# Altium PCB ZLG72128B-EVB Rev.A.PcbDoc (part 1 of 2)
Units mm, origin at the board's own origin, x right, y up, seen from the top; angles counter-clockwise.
Board outline 130 x 80 mm, 2 copper layers (Top Layer, Bottom Layer); 109 components, 70 nets, 433 pads, 399 vias.
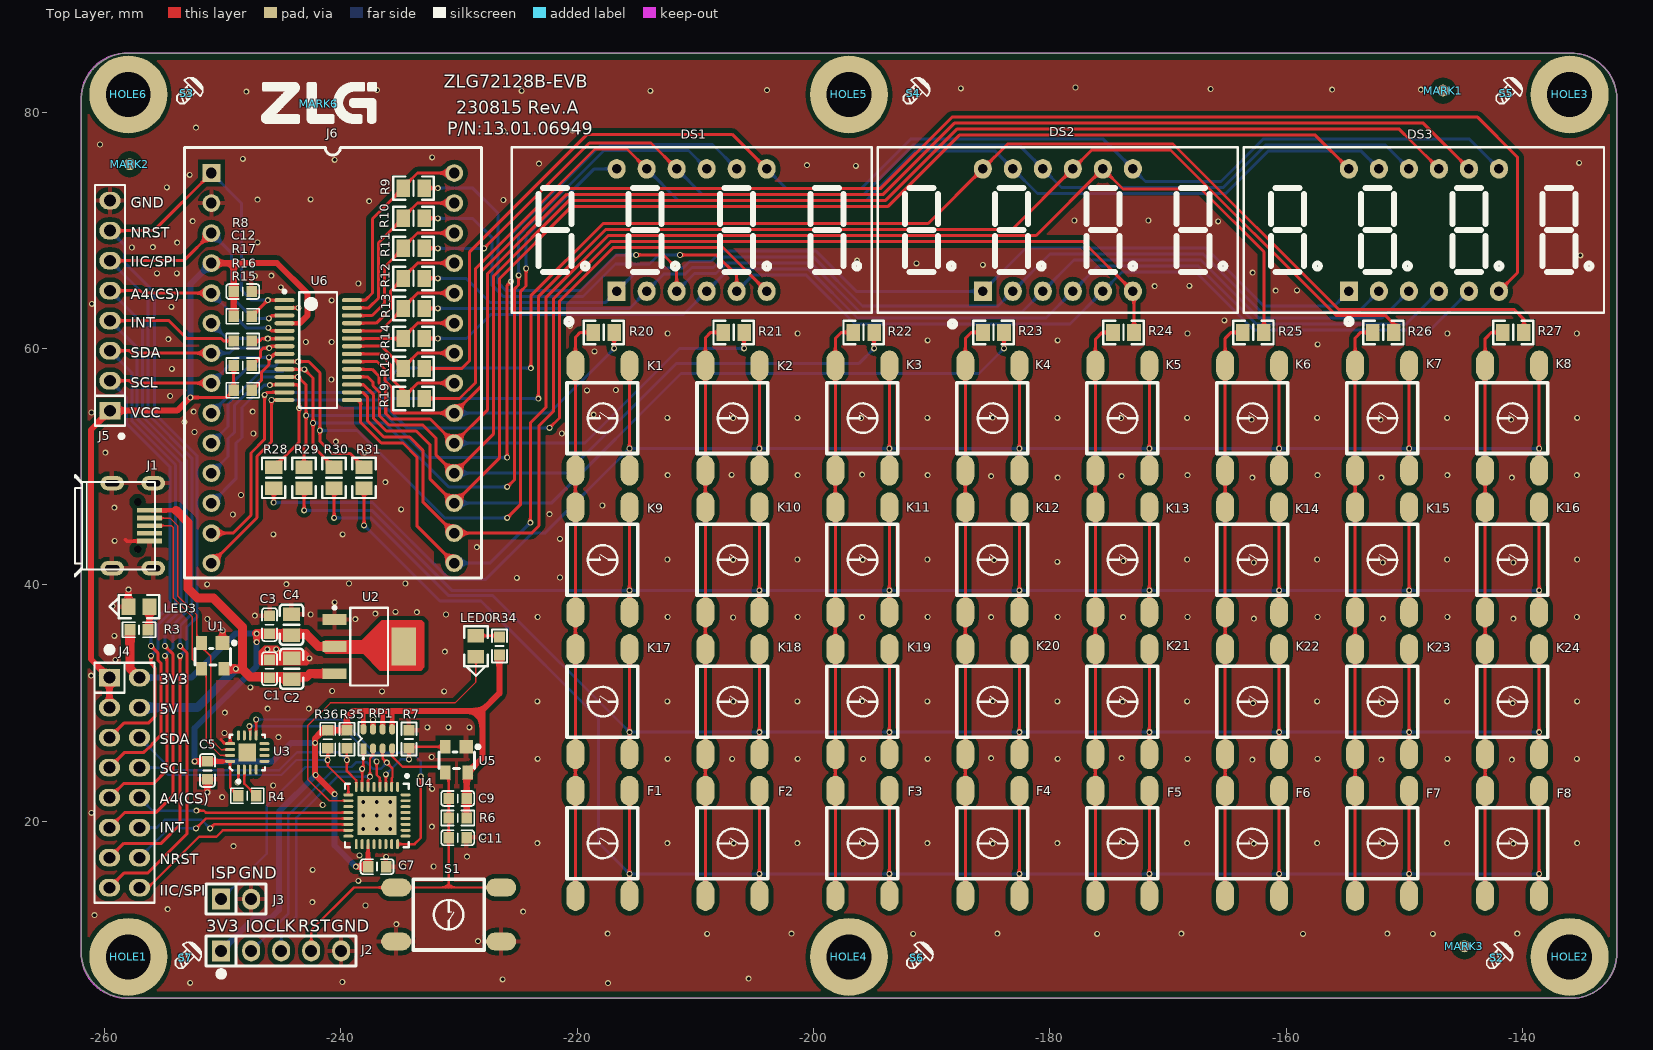
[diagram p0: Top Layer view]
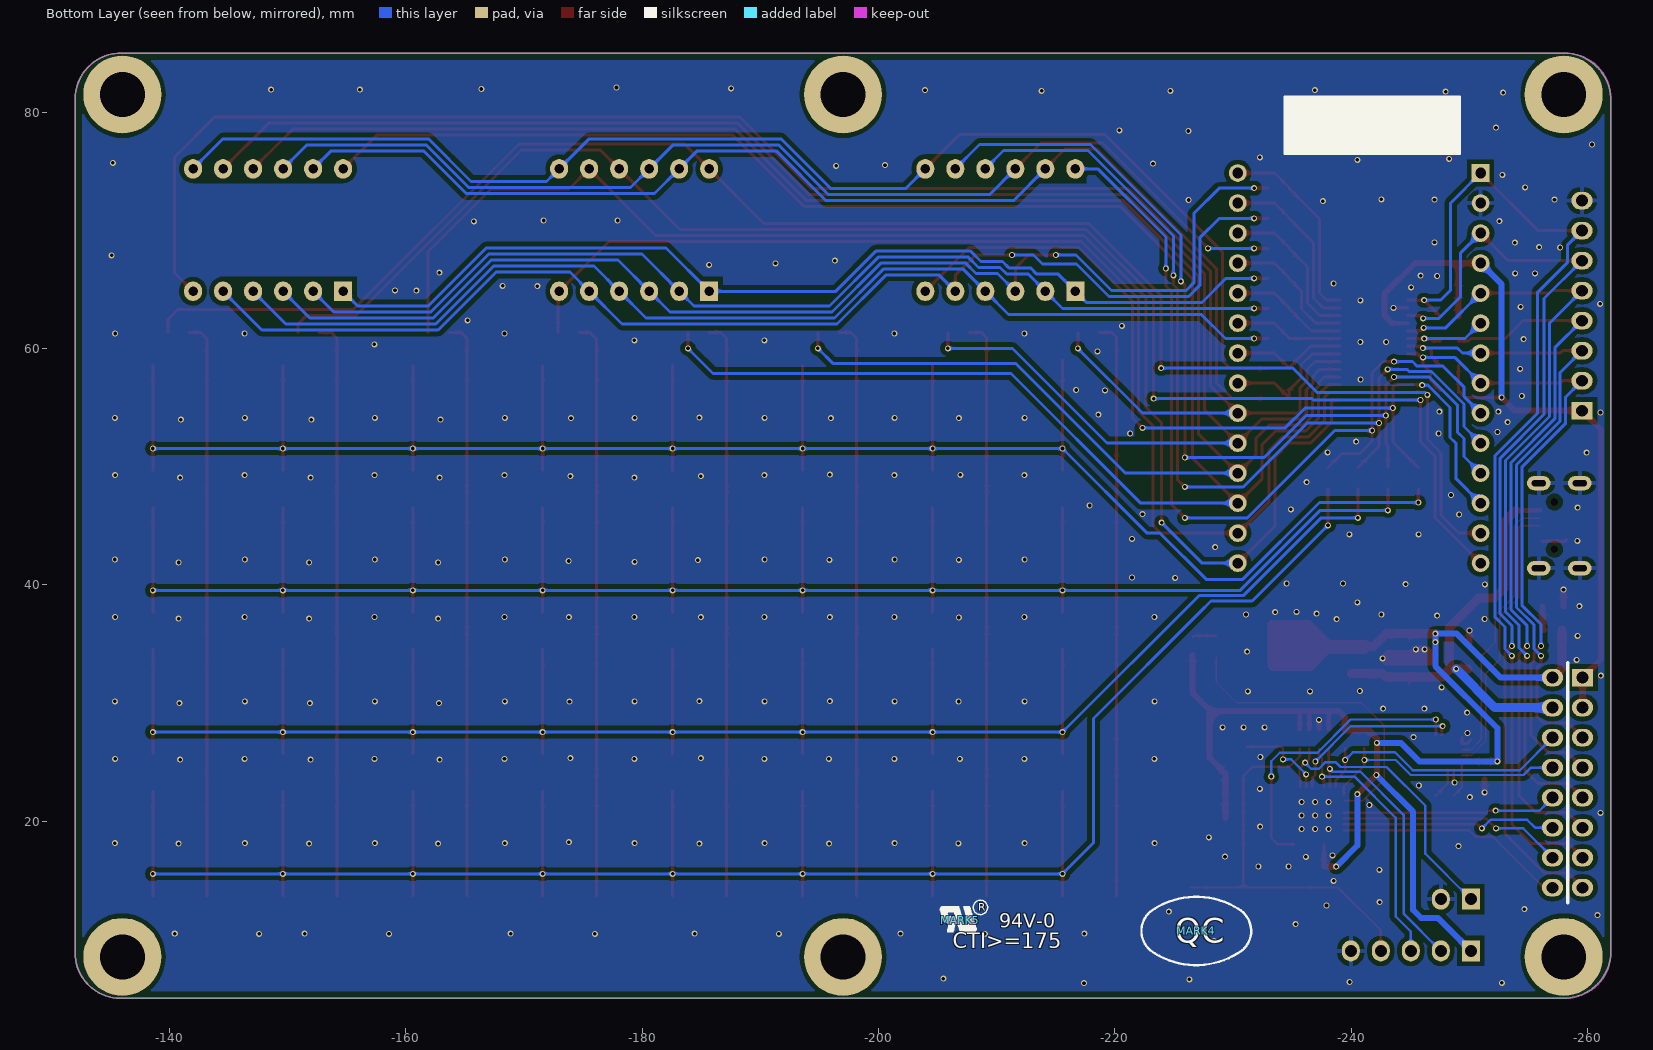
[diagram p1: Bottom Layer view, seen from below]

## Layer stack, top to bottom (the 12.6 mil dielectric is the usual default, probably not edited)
Top Solder: solder mask 0.0102, Solder Resist, Dk 3.5
Top Layer: signal copper 0.0356
Dielectric1: dielectric 0.32, FR-4, Dk 4.8
Bottom Layer: signal copper 0.0356
Bottom Solder: solder mask 0.0102, Solder Resist, Dk 3.5

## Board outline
-262,8.962 -262,80.911 cw(c-257.974,80.974) -258.038,85 -135.988,85 cw(c-135.912,81.088) -131.999,81.119 -132,81.119 -132,8.886 cw(c-135.848,8.848) -135.81,5 -257.911,5 cw(c-257.974,9.026)

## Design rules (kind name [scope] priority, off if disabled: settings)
Clearance Clearance_Keepout [OnLayer('Keep-Out Layer')] p1: gap=0.508 ignorepadtopadclearanceinfootprint=FALSE except(0: Arc-Hole Track-Hole SMDPad-Hole THPad-Hole Via-Hole Fill-Hole Poly-Hole Region-Hole Text-Hole)
Clearance Clearance_Wave [OnLayer('Bottom Layer') and IsSMTPin vs IsPadHoleValid>(HasFootprint('PAD-35/50') or HasFootprint('HOLE-3.2*') or HasFootprint('SMDSTUD-409D556W*') or    HasFootprint('SMT50L*FEMALE') or HasFootprint('IDCS*'))] p2: gap=4 ignorepadtopadclearanceinfootprint=FALSE except(0: Arc-Hole Track-Hole SMDPad-Hole THPad-Hole Via-Hole Fill-Hole Poly-Hole Region-Hole Text-Hole)
Clearance Clearance_Via2Via [IsVia vs IsVia] p3: gap=0.152 ignorepadtopadclearanceinfootprint=FALSE except(0: Arc-Hole Track-Hole SMDPad-Hole THPad-Hole Via-Hole Fill-Hole Poly-Hole Region-Hole Text-Hole)
Clearance Clearance_Poly2All [InPoly] p4: gap=0.381 ignorepadtopadclearanceinfootprint=FALSE except(0: Arc-Hole Track-Hole SMDPad-Hole THPad-Hole Via-Hole Fill-Hole Poly-Hole Region-Hole Text-Hole)
Clearance Clearance_TP [HasFootprint('PAD-40') vs HasFootprint('PAD-40')] p5: gap=1.27 ignorepadtopadclearanceinfootprint=FALSE except(0: Arc-Hole Track-Hole SMDPad-Hole THPad-Hole Via-Hole Fill-Hole Poly-Hole Region-Hole Text-Hole)
Clearance [All] p6: gap=0.127 ignorepadtopadclearanceinfootprint=FALSE except(0: Arc-Hole Track-Hole SMDPad-Hole THPad-Hole Via-Hole Fill-Hole Poly-Hole Region-Hole Text-Hole)
DiffPairsRouting [All] p1: maxlimit=0.203 minlimit=0.203 mostfreqgap=0.203 toplayer_minwidth=0.13 toplayer_maxwidth=0.13 toplayer_prefwidth=0.13 bottomlayer_minwidth=0.13 bottomlayer_maxwidth=0.13 bottomlayer_prefwidth=0.13 maxuncoupledlength=12.7
HoleSize [All] p1: absolutevalues=TRUE maxlimit=25.4 minlimit=0.025 maxpercent=80.000 minpercent=20.000
MinimumSolderMaskSliver [All] p1: minsoldermaskwidth=0.102
PlaneClearance PlaneClearance_Full [IsVia] p1: clearance=0.229
PlaneClearance [All] p2: clearance=0.508
PlaneConnect PlaneConnect_Full [IsVia] p1: planeconnectstyle=Direct reliefexpansion=0.508 reliefentries=4 reliefconductorwidth=0.254 reliefairgap=0.254
PlaneConnect [All] p2: planeconnectstyle=Relief reliefexpansion=0.254 reliefentries=4 reliefconductorwidth=0.381 reliefairgap=0.254
PolygonConnect PolygonConnect_SMDHole [HasFootprint('Mou Hole-300D450W310H-SMD') or HasFootprint('Mou Hole-373D600H-SMD')] p1: connectstyle=Relief reliefconductorwidth=2.032 reliefentries=4 polygonreliefangle="45 Angle" airgapwidth=0.508
PolygonConnect PolygonConnect_Full [IsVia or   HasFootprint('PAD-40') or  HasFootprint('PAD-35/50') or  HasFootprint('HOLE-3.2') or   HasFootprint('HOLE-3.2 - Screw')] p2: connectstyle=Direct reliefconductorwidth=0.254 reliefentries=4 polygonreliefangle="90 Angle" airgapwidth=0.254
PolygonConnect [All] p3: connectstyle=Relief reliefconductorwidth=0.381 reliefentries=4 polygonreliefangle="90 Angle" airgapwidth=0.381
RoutingVias [All] p1: holewidth=0.305 width=0.508 viastyle="Through Hole" minholewidth=0.305 minwidth=0.508 maxholewidth=0.305 maxwidth=0.508
SilkToSilkClearance [All  > IsTextInverted] p1: silktosilkclearance=0.051
SilkToSolderMaskClearance SilkToSolderMaskClearance_1 [IsComponentPad vs IsComponentArc or IsComponentTrack] p1: minsilkscreentomaskgap=0 clearancetoexposedcopper=TRUE
SilkToSolderMaskClearance [IsPad] p2: minsilkscreentomaskgap=0.051 clearancetoexposedcopper=TRUE
SolderMaskExpansion [All] p1: expansion=0.102 istentingtop=FALSE
Width [All] p1: maxlimit=2.54 minlimit=0.127 preferedwidth=0.127
23 further rules are at their usual default settings.

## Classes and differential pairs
component class "01.LPC824 最小系统": C7 C9 C11 HOLE1 HOLE2 HOLE3 HOLE4 HOLE5 HOLE6 HOLE? J2 J3 J4 MARK1 MARK2 MARK3 MARK4 MARK5 MARK6 MARK? R6 R7 R35 R36 RP1 S1 S2 S3 S4 S5 S6 S7 S? U4 U5
component class 02.ZLG72128B-key-digital: C12 DS1 DS2 DS3 F1 F2 F3 F4 F5 F6 F7 F8 J5 J6 K1 K2 K3 K4 K5 K6 K7 K8 K9 K10 K11 K12 K13 K14 K15 K16 K17 K18 K19 K20 K21 K22 K23 K24 R8 R9 R10 R11 R12 R13 R14 R15 R16 R17 R18 R19 R20 R21 R22 R23 R24 R25 R26 R27 R28 R29 R30 R31 U6
component class 03.USB和电源: C1 C2 C3 C4 C5 J1 LED0 LED3 R3 R4 R34 U1 U2 U3
differential pair USB: +USB_P -USB_N

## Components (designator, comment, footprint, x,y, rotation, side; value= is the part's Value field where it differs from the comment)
C1 "10μF,6.3V" 0603C -246.046,32.889 r90 top
C2 "105" 0805C -244.166,32.889 r270 top value=C2012X7R1E105KT000N,105
C3 "104,±10%" 0603C -246.046,36.623 r270 top
C4 "475,±10%" 0805C -244.192,36.623 r90 top
C5 "104,±10%" 0603C -251.306,24.291 r270 top
C7 "104,±10%" 0603C -236.941,16.139 r180 top
C9 "104,±10%" 0603C -230.12,21.916 r0 top
C11 "104,±10%" 0603C -230.12,18.589 r180 top
C12 "104" 0603C -248.313,64.817 r180 top value=104,±10%
DS1 "LN3461" LN3461-3000X1400X720 -210.308,70.024 r0 top locked value=LN3461AS,30×14×7.3mm
DS2 "LN3461" LN3461-3000X1400X720 -179.32,70.024 r0 top locked value=LN3461AS,30×14×7.3mm
DS3 "LN3461" LN3461-3000X1400X720 -148.332,70.024 r0 top locked value=LN3461AS,30×14×7.3mm
F1 "6×6×5.0mm,红色" KEY-6S -217.864,18.109 r270 top
F2 "6×6×5.0mm,红色" KEY-6S -206.864,18.109 r270 top
F3 "6×6×5.0mm,红色" KEY-6S -195.864,18.109 r270 top
F4 "6×6×5.0mm,红色" KEY-6S -184.864,18.109 r270 top
F5 "6×6×5.0mm,红色" KEY-6S -173.864,18.109 r270 top
F6 "6×6×5.0mm,红色" KEY-6S -162.864,18.109 r270 top
F7 "6×6×5.0mm,红色" KEY-6S -151.864,18.109 r270 top
F8 "6×6×5.0mm,红色" KEY-6S -140.864,18.109 r270 top
HOLE1 "HOLE" HOLE-3.8 -258,8.5 r0 top locked
HOLE2 "HOLE" HOLE-3.8 -136,8.5 r0 top locked
HOLE3 "HOLE" HOLE-3.8 -136,81.5 r0 top locked
HOLE4 "HOLE" HOLE-3.8 -197,8.5 r0 top locked
HOLE5 "HOLE" HOLE-3.8 -197,81.5 r0 top locked
HOLE6 "HOLE" HOLE-3.8 -258,81.5 r0 top locked
J1 "USB_MINIB_SMT" MICROUSB-5S -261.511,45 r270 top value=MicroUSB插座
J2 "SWD" SIP2.54-1X5 -245.055,9.013 r0 top
J3 "ISP" SIP2.54-1X2 -248.865,13.382 r0 top
J4 "HEADER 8X2" IDC-16-2.54 -259.595,32.14 r270 top locked
J5 "CON8" SIP-8-2.54 -259.543,54.733 r90 top locked
J6 "HEADER 14X2" zlg72128 -240.687,58.34 r0 top locked
K1 "6×6×5.0mm,黑色" KEY-6S -217.864,54.109 r270 top
K2 "6×6×5.0mm,黑色" KEY-6S -206.864,54.109 r270 top
K3 "6×6×5.0mm,黑色" KEY-6S -195.864,54.109 r270 top
K4 "6×6×5.0mm,黑色" KEY-6S -184.864,54.109 r270 top
K5 "6×6×5.0mm,黑色" KEY-6S -173.864,54.109 r270 top
K6 "6×6×5.0mm,黑色" KEY-6S -162.864,54.109 r270 top
K7 "6×6×5.0mm,黑色" KEY-6S -151.864,54.109 r270 top
K8 "6×6×5.0mm,黑色" KEY-6S -140.864,54.109 r270 top
K9 "6×6×5.0mm,黑色" KEY-6S -217.864,42.109 r270 top
K10 "6×6×5.0mm,黑色" KEY-6S -206.864,42.109 r270 top
K11 "6×6×5.0mm,黑色" KEY-6S -195.864,42.109 r270 top
K12 "6×6×5.0mm,黑色" KEY-6S -184.864,42.109 r270 top
K13 "6×6×5.0mm,黑色" KEY-6S -173.864,42.109 r270 top
K14 "6×6×5.0mm,黑色" KEY-6S -162.864,42.109 r270 top
K15 "6×6×5.0mm,黑色" KEY-6S -151.864,42.109 r270 top
K16 "6×6×5.0mm,黑色" KEY-6S -140.864,42.109 r270 top
K17 "6×6×5.0mm,黑色" KEY-6S -217.864,30.109 r270 top
K18 "6×6×5.0mm,黑色" KEY-6S -206.864,30.109 r270 top
K19 "6×6×5.0mm,黑色" KEY-6S -195.864,30.109 r270 top
K20 "6×6×5.0mm,黑色" KEY-6S -184.864,30.109 r270 top
K21 "6×6×5.0mm,黑色" KEY-6S -173.864,30.109 r270 top
K22 "6×6×5.0mm,黑色" KEY-6S -162.864,30.109 r270 top
K23 "6×6×5.0mm,黑色" KEY-6S -151.864,30.109 r270 top
K24 "6×6×5.0mm,黑色" KEY-6S -140.864,30.109 r270 top
LED0 "LED0" LED-0805 -228.571,34.794 r270 top value=绿色,0805
LED3 "LED1" LED-0805 -257.095,38.147 r180 top value=红色,0805
MARK1 "MARKER" MARKER-C-1.0M -146.707,81.835 r0 top
MARK2 "MARKER" MARKER-C-1.0M -257.882,75.587 r0 top
MARK3 "MARKER" MARKER-C-1.0M -144.903,9.394 r0 top
MARK4 "ZY QC" ZY_QC -226.9,10.7 r180 bottom
MARK5 "UR" ZY_UR-3X2 -206.9,11.6 r180 bottom
MARK6 "ZLGLOGO" ZLG0.5 -241.88,80.717 r0 top
R3 "1.5KΩ" 0603R -257.095,36.191 r0 top
R4 "4.7KΩ" 0603R -247.93,22.143 r0 top
R6 "10KΩ" 0603R -230.12,20.253 r0 top
R7 "100KΩ" 0603R -234.241,26.933 r270 top
R8 "4.7KΩ" 0603R -248.313,62.728 r180 top
R9 "200" 0805R -233.854,73.565 r0 top value=200Ω,±1%
R10 "200" 0805R -233.854,71.022 r0 top value=200Ω,±1%
R11 "200" 0805R -233.854,68.478 r0 top value=200Ω,±1%
R12 "200" 0805R -233.854,65.935 r0 top value=200Ω,±1%
R13 "200" 0805R -233.854,63.392 r0 top value=200Ω,±1%
R14 "200" 0805R -233.854,60.849 r0 top value=200Ω,±1%
R15 "4.7KΩ" 0603R -248.313,56.46 r180 top
R16 "4.7KΩ" 0603R -248.313,58.55 r180 top
R17 "200Ω" 0603R -248.313,60.639 r0 top
R18 "200" 0805R -233.854,58.305 r0 top value=200Ω,±1%
R19 "200" 0805R -233.854,55.762 r0 top value=200Ω,±1%
R20 "1K" 0805R -217.762,61.363 r0 top value=1KΩ,±1%
R21 "1K" 0805R -206.762,61.363 r0 top value=1KΩ,±1%
R22 "1K" 0805R -195.763,61.363 r0 top value=1KΩ,±1%
R23 "1K" 0805R -184.763,61.363 r0 top value=1KΩ,±1%
R24 "1K" 0805R -173.763,61.363 r0 top value=1KΩ,±1%
R25 "1K" 0805R -162.764,61.363 r0 top value=1KΩ,±1%
R26 "1K" 0805R -151.764,61.363 r0 top value=1KΩ,±1%
R27 "1K" 0805R -140.764,61.363 r0 top value=1KΩ,±1%
R28 "1K" 0805R -245.69,49.044 r270 top value=1KΩ,±1%
R29 "1K" 0805R -243.122,49.044 r270 top value=1KΩ,±1%
R30 "1K" 0805R -240.578,49.044 r270 top value=1KΩ,±1%
R31 "1K" 0805R -238.045,49.044 r270 top value=1KΩ,±1%
R34 "1.5KΩ" 0603R -226.59,34.82 r270 top
R35 "4.7KΩ" 0603R -239.493,26.92 r90 top
R36 "4.7KΩ" 0603R -241.118,26.92 r90 top
RP1 "10KΩ×4,SMD" 0603RA -236.883,26.952 r90 top
S1 "6×6×5.0mm,红色" KEY-6S -230.882,12.087 r180 top
S2 "=Value" Screw-Mark2 -142.185,8.429 r0 top
S3 "=Value" Screw-Mark2 -253.056,81.606 r0 top
S4 "=Value" Screw-Mark2 -191.538,81.606 r0 top
S5 "=Value" Screw-Mark2 -141.373,81.606 r0 top
S6 "=Value" Screw-Mark2 -191.258,8.429 r0 top
S7 "=Value" Screw-Mark2 -253.183,8.429 r0 top
U1 "PRTR5V0U2X" SOT-143 -250.847,33.981 r270 top
U2 "ZL6105A33S2" SOT229P700X180-4N -237.613,34.769 r0 top
U3 "XR21V1410IL16" QFN50P300X300X80-17AN -247.926,25.803 r90 top value=XR21V1410IL16TR-F
U4 "LPC824M201JHI33" QFN50P500X500X85-33N -236.953,20.469 r270 top
U5 "CAT811" SOT-143 -230.222,25.193 r270 top value=CAT811STBI
U6 "ZLG72128B" TSOP65P640X110-28N -241.931,59.864 r0 top

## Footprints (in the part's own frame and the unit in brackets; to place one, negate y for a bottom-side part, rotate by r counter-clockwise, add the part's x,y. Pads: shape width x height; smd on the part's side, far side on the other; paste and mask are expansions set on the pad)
0603C [mm]
  rect 0.9x0.95 smd: 1(-0.762,0) 2(0.762,0)
  silkscreen extent -1.4,-0.64 1.4,0.64, body extent -0.79,-0.38 0.81,0.42, height 0.3
0603R [mm]
  rect 0.9x0.95 smd: 1(-0.762,0) 2(0.762,0)
  silkscreen extent -1.4,-0.64 1.4,0.64, body extent -0.8,-0.4 0.8,0.4, height 0.3
0603RA [mil]
  rect 35x20 smd: 1(-32,48)
  oval 35x20 smd: 2(-32,16) 3(-32,-16) 4(-32,-48) 5(32,-48) 6(32,-16) 7(32,16) 8(32,48)
  silkscreen extent -66,-64 56,64, body extent -33,-63 33,63, height 22
0805C [mm]
  rect 1.15x1.45 smd: 1(-0.889,0) 2(0.889,0)
  silkscreen extent -1.7,-0.99 1.7,0.99, body extent -1,-0.63 1,0.63, height 0.78
0805R [mm]
  rect 1.15x1.45 smd: 1(-0.889,0) 2(0.889,0)
  silkscreen extent -1.7,-0.99 1.7,0.99, body extent -1,-0.63 1,0.63, height 0.78
HOLE-3.8 [mm]
  round 6.6 hole 3.8: 1(0,0)
IDC-16-2.54 [mm]
  rect 1.5x1.8 hole 1: 1(0,0)
  oval 1.5x1.8 hole 1: 2(0,2.54) 3(2.54,0) 4(2.54,2.54) 5(5.08,0) 6(5.08,2.54) 7(7.62,0) 8(7.62,2.54) 9(10.16,0) 10(10.16,2.54) 11(12.7,0) 12(12.7,2.54) 13(15.24,0) 14(15.24,2.54) 15(17.78,0) 16(17.78,2.54)
  silkscreen extent -2.61,-1.27 19.05,3.81, body extent -1.27,-1.27 19.05,3.81, height 7.58
KEY-6S [mil]
  oval 100x60 smd: 1(-175,90) 2(-175,-90) 3(175,-90) 4(175,90)
  silkscreen extent -118,-118 118,118, body extent -201,-122 201,122, height 268
LED-0805 [mm] "130513 缩短焊盘及丝印，和0805电阻一样LSB"
  rect 1.15x1.4 smd: 1(-0.889,0) 2(0.889,0)
  silkscreen extent -1.7,-0.99 2.49,0.99, body extent -1,-0.64 1,0.64, height 1.1
LN3461-3000X1400X720 [mm]
  rect 1.524x1.651 hole 0.8: 1(-6.35,-5.18)
  oval 1.524x1.651 hole 0.8: 2(-3.81,-5.18) 3(-1.27,-5.18) 4(1.27,-5.18) 5(3.81,-5.18) 6(6.35,-5.18) 7(6.35,5.18) 8(3.81,5.18) 9(1.27,5.18) 10(-1.27,5.18) 11(-3.81,5.18) 12(-6.35,5.18)
  silkscreen extent -15.24,-8 15.24,7
MARKER-C-1.0M [mm]
  round 1 smd paste-1.016 mask+0.5: 0(0,0)
  Top Layer pour cut-out: -1.1,0 -1.016,-0.421 -0.778,-0.778 -0.421,-1.016 0,-1.1 0,-1.1 0.421,-1.016 0.778,-0.778 1.016,-0.421 1.1,0 1.1,0 1.016,0.421 0.778,0.778 0.421,1.016 0,1.1 0,1.1 -0.421,1.016 -0.778,0.778 -1.016,0.421 -1.1,0
MICROUSB-5S [mm]
  oval 1.2x2 on Top Paste: 0(-3.6,2.15) 0(-3.6,5.62) 0(3.6,2.15) 0(3.6,5.62)
  round 0.54 hole 0.65 unplated: 0(-2,4.3) 0(2,4.3)
  rect 0.4x2.15 smd: 1(-1.3,5.31) 2(-0.65,5.31) 3(0,5.31) 4(0.65,5.31) 5(1.3,5.31)
  oval 1.2x2 hole 0.5 slot 1.2 at 90 deg: 6(-3.6,5.62) 7(3.6,5.62) 8(-3.6,2.15) 9(3.6,2.15)
  silkscreen extent -4.3,-0.99 4.3,5.77
QFN50P300X300X80-17AN [mm]
  oval 0.85x0.25 smd: 1(-1.45,0.75) 2(-1.45,0.25) 3(-1.45,-0.25) 4(-1.45,-0.75) 9(1.45,-0.75) 10(1.45,-0.25) 11(1.45,0.25) 12(1.45,0.75)
  oval 0.25x0.85 smd: 5(-0.75,-1.45) 6(-0.25,-1.45) 7(0.25,-1.45) 8(0.75,-1.45) 13(0.75,1.45) 14(0.25,1.45) 15(-0.25,1.45) 16(-0.75,1.45)
  rect 1.5x1.5 smd paste-0.3: 17(0,0)
  silkscreen extent -2.57,-1.5 1.5,1.5
QFN50P500X500X85-33N [mm] "QFN, 32-Leads, Body 5.00x5.00mm, Pitch 0.50mm, Thermal Pad 3.60x3.60mm, IPC Medium Density"
  oval 0.85x0.25 smd: 1(-2.425,1.75) 2(-2.425,1.25) 3(-2.425,0.75) 4(-2.425,0.25) 5(-2.425,-0.25) 6(-2.425,-0.75) 7(-2.425,-1.25) 8(-2.425,-1.75) 17(2.425,-1.75) 18(2.425,-1.25) 19(2.425,-0.75) 20(2.425,-0.25) 21(2.425,0.25) 22(2.425,0.75) 23(2.425,1.25) 24(2.425,1.75)
  oval 0.25x0.85 smd: 9(-1.75,-2.425) 10(-1.25,-2.425) 11(-0.75,-2.425) 12(-0.25,-2.425) 13(0.25,-2.425) 14(0.75,-2.425) 15(1.25,-2.425) 16(1.75,-2.425) 25(1.75,2.425) 26(1.25,2.425) 27(0.75,2.425) 28(0.25,2.425) 29(-0.25,2.425) 30(-0.75,2.425) 31(-1.25,2.425) 32(-1.75,2.425)
  rect 3.3x3.3 smd: 33(0,0)
  silkscreen extent -3.47,-2.7 2.7,2.7, body extent -2.55,-2.55 2.55,2.55, height 0.85
Screw-Mark2 [mm]
  silkscreen extent -0.83,-0.88 1.37,1.32
SIP2.54-1X2 [mil]
  rect 60x70 hole 40: 1(-50,0)
  oval 60x70 hole 40: 2(50,0)
  silkscreen extent -100,-50 100,50, body extent -100,-50 100,50, height 298
SIP2.54-1X5 [mil]
  rect 60x70 hole 40: 1(-200,0)
  oval 60x70 hole 40: 2(-100,0) 3(0,0) 4(100,0) 5(200,0)
  silkscreen extent -250,-86 249,50, body extent -250,-50 250,50, height 298
SIP-8-2.54 [mm]
  rect 1.5x1.8 hole 1: 1(0,0)
  oval 1.5x1.8 hole 1: 2(2.54,0) 3(5.08,0) 4(7.62,0) 5(10.16,0) 6(12.7,0) 7(15.24,0) 8(17.78,0)
  silkscreen extent -2.28,-1.27 19.1,1.27, body extent -1.27,-1.27 19.05,1.27, height 7.58
SOT229P700X180-4N [mm] "SOT223, 4-Leads, Body 6.50x7.00mm (avg), Pitch 2.29mm, IPC Medium Density,ZLGLIB"
  rect 2.05x0.9 smd: 1(-2.925,2.286) 2(-2.925,0) 3(-2.925,-2.286)
  rect 2.05x3.2 smd: 4(2.925,0)
  silkscreen extent -3.05,-3.3 1.6,3.41, body extent -3.5,-3.3 3.5,3.3, height 1.8
SOT-143 [mil] "SOT-143B"
  rect 46x46 smd: 1(-43,32.5)
  rect 46x36 smd: 2(-43,-37.5) 3(43,-37.5) 4(43,37.5)
  silkscreen extent -49,-59 30,77
TSOP65P640X110-28N [mm] "TSOP, 28-Leads, Body 9.8x4.5mm (max), Pitch 0.65mm, IPC Medium Density"
  oval 1.7x0.35 smd: 1(-2.85,4.225) 2(-2.85,3.575) 3(-2.85,2.925) 4(-2.85,2.275) 5(-2.85,1.625) 6(-2.85,0.975) 7(-2.85,0.325) 8(-2.85,-0.325) 9(-2.85,-0.975) 10(-2.85,-1.625) 11(-2.85,-2.275) 12(-2.85,-2.925) 13(-2.85,-3.575) 14(-2.85,-4.225) 15(2.85,-4.225) 16(2.85,-3.575) 17(2.85,-2.925) 18(2.85,-2.275) 19(2.85,-1.625) 20(2.85,-0.975) 21(2.85,-0.325) 22(2.85,0.325) 23(2.85,0.975) 24(2.85,1.625) 25(2.85,2.275) 26(2.85,2.925) 27(2.85,3.575) 28(2.85,4.225)
  silkscreen extent -2.97,-4.9 1.6,5.07, body extent -2.25,-4.9 2.25,4.9, height 1.1
ZLG0.5 [mm]
  silkscreen extent -4.87,-1.65 4.93,1.83
zlg72128 [mm]
  rect 1.5x1.5 hole 0.9: 1(-10.276,16.51)
  round 1.5 hole 0.9: 2(-10.276,13.97) 3(-10.276,11.43) 4(-10.276,8.89) 5(-10.276,6.35) 6(-10.276,3.81) 7(-10.276,1.27) 8(-10.276,-1.27) 9(-10.276,-3.81) 10(-10.276,-6.35) 11(-10.276,-8.89) 12(-10.276,-11.43) 13(-10.276,-13.97) 14(-10.276,-16.51) 15(10.276,-16.51) 16(10.276,-13.97) 17(10.276,-11.43) 18(10.276,-8.89) 19(10.276,-6.35) 20(10.276,-3.81) 21(10.276,-1.27) 22(10.276,1.27) 23(10.276,3.81) 24(10.276,6.35) 25(10.276,8.89) 26(10.276,11.43) 27(10.276,13.97) 28(10.276,16.51)
  silkscreen extent -12.56,-17.78 12.58,18.67
ZY_QC [mm]
  silkscreen extent -4.64,-2.89 4.64,2.89
ZY_UR-3X2 [mm]
  silkscreen extent -1.7,-1.02 2.33,1.7

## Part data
C1: library part 1.02.01.0065, "10μF,6.3V,X5R,GRM188R60J106M****,0603,Murata,RoHS"
C2: library part 1.02.02.0044, "C2012X7R1E105KT000N,105,±10%,25V,X7R,0805,TDK,RoHS"
C3 C5 C7 C9 C11 C12: library part 1.02.01.0032, "104,±10%,50V,X7R,0603,*,RoHS"
C4: library part 1.02.02.0064, "475,±10%,16V,X7R,0805,RoHS"
DS1 DS2 DS3: library part 1.08.01.0003, "LN3461AS,30×14×7.3mm,四位共阴,RoHS"
F1 F2 F3 F4 F5 F6 F7 F8 S1: library part 1.09.01.0004, "6×6×5.0mm,红色,SMD,*"
J1: "A01SB141B1-261,MicroUSB插座,SMT,艾立信,RoHS"
J2: library part "Header 5H", "Header, 5-Pin, Right Angle"
J3: library part "Header 2H", "Header, 2-Pin, Right Angle"
J5: "Connector"
K1 K2 K3 K4 K5 K6 K7 K8 K9 K10 K11 K12 K13 K14 K15 K16 K17 K18 K19 K20 K21 K22 K23 K24: library part 1.09.01.0003, "6×6×5.0mm,黑色,SMD,,*"
LED0: library part 1.04.05.0002, "绿色,0805,0805,RoHS"
LED3: library part 1.04.05.0001, "红色,0805,0805,RoHS"
MARK6: "ZLGLIB"
R3 R34: library part 1.01.01.0037, "1.5KΩ,0603,*,RoHS"
R4 R8 R15 R16 R35 R36: library part 1.01.01.0045, "4.7KΩ,0603,*,RoHS"
R6: library part 1.01.01.0051, "10KΩ,0603,*,RoHS"
R7: library part 1.01.01.0062, "100KΩ,0603,*,RoHS"
R9 R10 R11 R12 R13 R14 R18 R19: library part 1.01.02.0121, "200Ω,±1%,0805,*,RoHS"
R17: library part 1.01.01.0026, "200Ω,0603,*,RoHS"
R20 R21 R22 R23 R24 R25 R26 R27 R28 R29 R30 R31: library part 1.01.02.0045, "1KΩ,±1%,0805,*,RoHS"
RP1: library part 1.01.04.0004, "10KΩ×4,SMD,PZ-4-0.8,RoHS"
S2 S3 S4 S5 S6 S7: library part Screw-Mark
U1: library part 1.05.10.0153, "PRTR5V0U2X,SOT-143B,NXP,RoHS"
U2: library part 89.12.00022
U3: library part 1.05.08.0043, "XR21V1410IL16TR-F,QFN-16,EXAR"
U4: library part 1.05.01.0105, "LPC824M201JHI33,HVQFN-33,NXP,RoHS"
U5: library part 1.05.07.0023, "CAT811STBI,SOT-143,ON,RoHS"

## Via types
v1: diameter 0.508, hole 0.305, Top Layer to Bottom Layer, tented both sides, 399 vias

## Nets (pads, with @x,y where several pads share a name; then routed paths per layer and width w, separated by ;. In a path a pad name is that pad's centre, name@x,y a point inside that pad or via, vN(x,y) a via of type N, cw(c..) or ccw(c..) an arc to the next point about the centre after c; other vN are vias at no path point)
3.3V: C3.2 C4.1 C5.1 C7.2 C9.2 J2.1 J4.2 R3.1 R4.1 R6.2 R34.2 R35.2 R36.2 RP1.5 RP1.6 RP1.8 U2.2 U2.4 U3.16 U4.19 U5.4 | length 129.6
  Top Layer w0.203: -250.008,25.053 U3.16@-249.376,25.053 -249.376,22.827 R4.1@-248.692,22.143 ; -237.703,17.319 U4.19@-237.703,18.044
  Top Layer w0.381: RP1.8@-238.102,27.765 -238.102,29.276 ; RP1.6@-236.477,27.765 -236.477,29.301 ; RP1.5@-235.664,27.765 -235.664,29.327
  Top Layer w0.406: C5.1@-251.306,25.053 -250.008,25.053 ; C7.2@-237.703,16.139 -237.703,17.319
  Top Layer w0.508: v1(-252.383,25.053) C5.1@-251.306,25.053 ; v1(-247.138,35.138) v1(-247.138,35.861) ; v1(-240.534,22.272) -242.185,23.923 v1(-242.185,26.615) -242.185,26.996 -241.499,27.682 R36.2@-241.118,27.682 R35.2@-239.493,27.682 -239.493,28.8 -238.959,29.333 -228.799,29.333 ; v1(-238.743,16.139) C7.2@-237.703,16.139 ; R6.2@-229.358,20.253 C9.2@-229.358,21.916 -229.358,24.012 U5.4@-229.269,24.101 -228.037,25.333 -228.037,28.571 ; R34.2@-226.59,34.058 -226.59,30.806 -228.063,29.333 ; -228.799,29.333 -228.037,28.571 ; -228.799,29.333 -228.063,29.333 ; -228.063,29.333 -228.037,29.308 -228.037,28.571
  Top Layer w0.762: R3.1@-257.857,36.191 -257.857,32.942 J4.2@-257.055,32.14 ; v1(-247.138,35.861) C3.2@-246.046,35.861 -242.973,35.861 -241.88,34.769 U2.2@-240.538,34.769 U2.4@-235.2,34.769
  Bottom Layer w0.508: J4.2@-257.055,32.14 -252.663,32.14 -248.942,35.861 v1(-247.138,35.861) -247.138,33.118 -252.383,27.873 v1(-252.383,25.053) -245.78,25.053 -244.217,26.615 v1(-242.185,26.615) ; J2.1@-250.135,9.013 -247.341,11.807 -245.919,11.807 -245.259,12.468 -245.259,20.773 v1(-242.134,23.898) ; v1(-240.534,22.272) -240.534,17.93 v1(-238.743,16.139)
5V: C1.1 C2.2 J1.1 J4.4 U1.4 U2.3 | length 38.3
  Top Layer w0.381: J1.1@-256.001,46.3 -253.97,46.3
  Top Layer w0.762: -253.958,46.288 -252.955,45.284 -252.955,39.696 -252.125,38.867 -250.787,38.867 -248.332,36.411 -248.332,32.838 -247.697,32.203 -242.896,32.203 -242.617,32.483 U2.3@-240.538,32.483 U2.3@-240.026,32.483 ; U1.4@-249.894,32.889 v1(-248.891,32.889) -248.383,32.889
  Bottom Layer w0.762: J4.4@-257.055,29.6 -252.18,29.6 v1(-248.891,32.889)
A: DS1.11 DS2.11 DS3.11 R19.2 | length 102.4
  Top Layer w0.254: R19.2@-232.965,55.762 -229.955,55.762 -228.596,57.121 -228.596,66.773 -218.487,76.882 -215.796,76.882 DS1.11@-214.118,75.204
  Bottom Layer w0.254: DS1.11@-214.118,75.204 -211.427,72.513 -195.551,72.513 -191.334,76.73 -184.656,76.73 DS2.11@-183.13,75.204 -181.049,73.123 -165.096,73.123 -161.489,76.73 -153.668,76.73 DS3.11@-152.142,75.204
A4(CS): J4.9 J5.5 J6.5 U6.5 | length 66.1
  Top Layer w0.254: J4.9@-259.595,21.98 -258.389,23.186 -255.85,23.186 -254.737,24.3 -254.737,33.807 v1(-254.911,33.981) ; J5.5@-259.543,64.893 -257.003,64.893 -256.8,64.69 J6.5@-250.963,64.69 ; v1(-246.148,61.744) -245.893,61.489 U6.5@-244.781,61.489
  Bottom Layer w0.254: J5.5@-259.543,64.893 -256.79,62.14 -256.79,54.235 -253.082,50.526 -253.082,37.706 -254.199,36.588 -254.199,34.693 v1(-254.911,33.981) ; J6.5@-250.963,64.69 -248.017,61.744 v1(-246.148,61.744)
B: DS1.7 DS2.7 DS3.7 R18.2 | length 112.3
  Top Layer w0.254: R18.2@-232.965,58.305 -229.774,58.305 -229.104,58.975 -229.104,68.177 -219.155,78.127 -206.881,78.127 DS1.7@-203.958,75.204
  Bottom Layer w0.254: DS1.7@-203.958,75.204 -202.283,73.529 -195.972,73.529 -191.755,77.746 -175.512,77.746 DS2.7@-172.97,75.204 -171.905,74.139 -165.517,74.139 -161.91,77.746 -144.524,77.746 DS3.7@-141.982,75.204
C: DS1.4 DS2.4 DS3.4 R14.2 | length 95.1
  Top Layer w0.254: R14.2@-232.965,60.849 v1(-231.802,60.849)
  Bottom Layer w0.254: v1(-231.802,60.849) -229.364,60.849 -227.329,62.884 -210.998,62.884 DS1.4@-209.038,64.844 -207.135,66.747 -200.446,66.747 -196.28,62.582 -180.312,62.582 DS2.4@-178.05,64.844 -175.918,66.976 -167.426,66.976 -162.524,62.074 -149.832,62.074 DS3.4@-147.062,64.844
COM0: DS3.6 J6.20 R20.2 U6.20 | length 148.8
  Top Layer w0.254: U6.20@-239.081,58.889 -236.943,58.889 -236.267,58.213 -236.267,57.272 -235.699,56.704 -235.699,54.699 -235.53,54.53 J6.20@-230.41,54.53 -228.088,56.852 -228.088,66.562 -221.096,73.555 -194.306,73.555 -188.286,79.574 -143.786,79.574 -140.407,76.196 -140.407,66.419 DS3.6@-141.982,64.844 ; v1(-216.873,60.005) R20.2@-216.873,61.363
  Bottom Layer w0.254: J6.20@-230.41,54.53 -222.348,54.53 v1(-216.873,60.005)
COM1: DS3.8 J6.19 R21.2 U6.19 | length 147.5
  Top Layer w0.254: U6.19@-239.081,58.239 -237.36,58.239 -236.775,57.654 -236.775,57.062 -236.207,56.494 -236.207,54.488 -235.741,54.022 -232.442,54.022 J6.19@-230.41,51.99 -227.58,54.82 -227.58,66.352 -220.886,73.047 -194.096,73.047 -188.076,79.066 -148.385,79.066 DS3.8@-144.522,75.204 ; v1(-205.873,60.005) R21.2@-205.873,61.363
  Bottom Layer w0.254: J6.19@-230.41,51.99 -219.351,51.99 -211.336,60.005 v1(-205.873,60.005)
COM2: DS3.9 J6.18 R22.2 U6.18 | length 160.1
  Top Layer w0.254: U6.18@-239.081,57.589 -237.726,57.589 -237.283,57.146 -237.283,56.851 -236.715,56.283 -236.715,54.278 -235.951,53.514 -233.067,53.514 -231.974,52.422 -231.974,51.014 J6.18@-230.41,49.45 -227.072,52.788 -227.072,66.142 -220.675,72.539 -193.885,72.539 -187.866,78.558 -157.318,78.558 -150.417,78.558 -149.426,77.568 DS3.9@-147.062,75.204 ; v1(-194.874,60.005) R22.2@-194.874,61.363
  Bottom Layer w0.254: J6.18@-230.41,49.45 -220.9,49.45 -211.604,58.746 -196.132,58.746 v1(-194.874,60.005)
COM3: DS3.12 J6.17 R23.2 U6.17 | length 167.7
  Top Layer w0.254: U6.17@-239.081,56.939 -238.089,56.939 -237.223,56.073 -237.223,54.067 -236.162,53.006 -233.625,53.006 -232.482,51.863 -232.482,48.982 J6.17@-230.41,46.91 -226.564,50.756 -226.564,65.931 -220.465,72.031 -193.675,72.031 -187.655,78.05 -157.529,78.05 DS3.12@-154.682,75.204 ; v1(-183.874,60.005) R23.2@-183.874,61.363
  Bottom Layer w0.254: J6.17@-230.41,46.91 -222.195,46.91 -211.223,57.883 -185.996,57.883 v1(-183.874,60.005)
COM4: DS2.6 J6.16 R24.2 U6.16 | length 100.8
  Top Layer w0.254: U6.16@-239.081,56.289 -238.157,56.289 -237.731,55.863 -237.731,53.857 -236.372,52.498 -234.184,52.498 -233.067,51.38 -233.067,47.026 J6.16@-230.41,44.37 -223.872,44.37 -223.237,45.005 -223.237,53.463 -222.018,54.682 -222.018,64.211 -217.17,69.059 -177.185,69.059 DS2.6@-172.97,64.844 -172.874,64.748 R24.2@-172.874,61.363
COM5: DS2.8 J6.15 R25.2 U6.15 | length 121.3
  Top Layer w0.254: U6.15@-239.081,55.639 -238.415,55.639 -238.338,55.563 -238.338,53.746 -236.582,51.99 -234.743,51.99 -233.575,50.822 -233.575,44.994 J6.15@-230.41,41.83 ; v1(-223.973,45.259) -223.973,53.692 -222.653,55.013 -222.653,64.295 -217.38,69.567 -181.147,69.567 DS2.8@-175.51,75.204 -173.81,73.504 -167.193,73.504 -161.875,68.185 R25.2@-161.875,61.363
  Bottom Layer w0.254: J6.15@-230.41,41.83 -227.402,41.83 v1(-223.973,45.259)
COM6: DS2.9 J6.14 R26.2 U6.14 | length 133.1
  Top Layer w0.254: J6.14@-250.963,41.83 -247.113,45.68 -247.113,50.872 -245.877,52.108 v1(-245.877,55.639) U6.14@-244.781,55.639 ; v1(-223.288,55.749) -223.288,64.378 -217.591,70.075 -183.179,70.075 DS2.9@-178.05,75.204 -176.448,76.806 -169.777,76.806 -155.782,62.81 -151.609,62.81 -150.875,62.076 R26.2@-150.875,61.363
  Bottom Layer w0.254: v1(-245.877,55.639) -236.809,55.639 -236.699,55.749 -235.607,55.749 ; -236.013,55.749 -235.607,55.749 ; v1(-223.288,55.749) -235.607,55.749
COM7: DS2.12 J6.13 R27.2 U6.13 | length 142.6
  Top Layer w0.254: J6.13@-250.963,44.37 -249.142,44.37 -247.621,45.891 -247.621,51.152 -246.465,52.308 v1(-246.465,56.067) -246.243,56.289 U6.13@-244.781,56.289 ; v1(-223.923,58.34) -223.923,64.461 -217.801,70.583 -190.291,70.583 DS2.12@-185.67,75.204 -183.56,77.314 -169.567,77.314 -155.571,63.318 -140.712,63.318 -139.875,62.481 R27.2@-139.875,61.363
  Bottom Layer w0.254: v1(-246.465,56.067) -246.243,56.289 -237.124,56.289 -235.073,58.34 v1(-223.923,58.34)
COM8: DS1.6 J6.12 R28.1 U6.12 | length 76.5
  Top Layer w0.254: v1(-246.021,56.892) -245.974,56.939 U6.12@-244.781,56.939 -243.709,56.939 -243.531,56.761 v1(-243.531,54.962) -243.531,52.092 R28.1@-245.69,49.933 ; v1(-222.348,53.285) -221.51,54.124 -221.51,64.001 -216.96,68.551 -207.665,68.551 DS1.6@-203.958,64.844
  Bottom Layer w0.254: J6.12@-250.963,46.91 -248.865,49.008 -248.865,51.99 -248.383,52.473 -248.383,55.013 -246.503,56.892 v1(-246.021,56.892) ; v1(-243.531,54.962) -236.115,54.962 -234.438,53.285 v1(-222.348,53.285)
COM9: DS1.8 J6.11 R29.1 U6.11 | length 82.7
  Top Layer w0.254: U6.11@-244.781,57.589 v1(-243.633,57.589) -242.947,56.903 -242.947,51.939 -243.122,51.765 R29.1@-243.122,49.933 ; v1(-225.929,50.771) -225.929,65.35 v1(-225.599,65.681)
  Bottom Layer w0.254: J6.11@-250.963,49.45 -249.551,50.862 -249.551,52.371 -248.992,52.93 -248.992,55.208 -246.611,57.589 v1(-243.633,57.589) ; v1(-242.947,54.327) -236.198,54.327 -232.642,50.771 v1(-225.929,50.771) ; v1(-225.599,65.681) -225.599,69.599 -217.935,77.263 -208.557,77.263 DS1.8@-206.498,75.204
COM10: DS1.9 J6.10 R30.1 U6.10 | length 82.5
  Top Layer w0.254: U6.10@-244.781,58.239 v1(-243.1,58.239) -242.363,57.502 -242.363,51.717 R30.1@-240.578,49.933 ; v1(-225.929,48.282) -225.294,48.917 -225.294,65.046 -224.964,65.376 v1(-224.964,66.189)
  Bottom Layer w0.254: J6.10@-250.963,51.99 -249.551,53.402 -249.551,55.295 -246.8,58.046 -244.899,58.046 -244.706,58.239 v1(-243.1,58.239) ; v1(-242.363,53.692) -236.281,53.692 -230.871,48.282 v1(-225.929,48.282) ; v1(-224.964,66.189) -224.964,69.516 -217.725,76.755 -210.589,76.755 DS1.9@-209.038,75.204
COM11: DS1.12 J6.9 R31.1 U6.9 | length 76.8
  Top Layer w0.254: U6.9@-244.781,58.889 v1(-243.633,58.889) -242.725,58.889 -241.779,57.943 -241.779,52.142 -240.737,51.101 -239.213,51.101 R31.1@-238.045,49.933 ; v1(-225.929,45.665) -224.786,46.808 -224.786,64.835 -224.329,65.292 v1(-224.329,66.773)
  Bottom Layer w0.254: J6.9@-250.963,54.53 -249.577,55.916 -249.577,56.714 -247.788,58.503 -245.578,58.503 -245.192,58.889 v1(-243.633,58.889) ; v1(-241.779,53.057) -238.629,53.057 -231.238,45.665 v1(-225.929,45.665) ; v1(-224.329,66.773) -224.329,69.433 -218.558,75.204 DS1.12@-216.658,75.204
D: DS1.2 DS2.2 DS3.2 R13.2 | length 89.8
  Top Layer w0.254: R13.2@-232.965,63.392 v1(-231.802,63.392)
  Bottom Layer w0.254: v1(-231.802,63.392) -230.222,63.392 ; -231.117,63.392 -230.222,63.392 ; DS3.2@-152.142,64.844 -153.896,63.09 -162.103,63.09 -167.005,67.992 -179.982,67.992 DS2.2@-183.13,64.844 -184.376,63.598 -195.859,63.598 -200.025,67.763 -207.556,67.763 -208.47,66.849 -210.292,66.849 -210.825,66.316 -212.647,66.316 DS1.2@-214.118,64.844 -215.57,63.392 -230.222,63.392
DP: DS1.3 DS2.3 DS3.3 R9.2 | length 101.5
  Top Layer w0.254: R9.2@-232.965,73.565 v1(-231.802,73.565) ; v1(-215.007,67.916) -212.696,67.916 -211.578,66.798 DS1.3@-211.578,64.844
  Bottom Layer w0.254: v1(-231.802,73.565) -228.835,73.565 -226.691,71.421 -226.691,65.561 -226.046,64.916 -219.716,64.916 -216.716,67.916 v1(-215.007,67.916) ; DS1.3@-211.578,64.844 -210.081,66.341 -208.26,66.341 -207.345,67.255 -200.235,67.255 -196.07,63.09 -182.344,63.09 DS2.3@-180.59,64.844 -177.95,67.484 -167.215,67.484 -162.313,62.582 -151.864,62.582 DS3.3@-149.602,64.844
E: DS1.1 DS2.1 DS3.1 R12.2 | length 86.4
  Top Layer w0.254: R12.2@-232.965,65.935 v1(-231.802,65.935)
  Bottom Layer w0.254: v1(-231.802,65.935) -229.41,65.935 -227.374,63.9 -217.602,63.9 DS1.1@-216.658,64.844 -215.183,66.319 -213.362,66.319 -212.857,66.824 -211.035,66.824 -210.502,67.357 -208.68,67.357 -207.766,68.271 -199.815,68.271 -196.387,64.844 DS2.1@-185.67,64.844 -182.014,68.5 -166.795,68.5 -161.892,63.598 -155.928,63.598 DS3.1@-154.682,64.844
F: DS1.10 DS2.10 DS3.10 R11.2 | length 96.4
  Top Layer w0.254: R11.2@-232.965,68.478 v1(-231.802,68.478) ; v1(-227.889,68.478) -218.977,77.39 -217.446,77.39 ; -218.697,77.39 -217.446,77.39 ; DS1.10@-211.578,75.204 -213.764,77.39 -217.446,77.39
  Bottom Layer w0.254: v1(-231.802,68.478) -230.45,68.478 ; -231.117,68.478 -230.45,68.478 ; v1(-227.889,68.478) -230.45,68.478 ; DS1.10@-211.578,75.204 -209.395,73.021 -195.761,73.021 -191.545,77.238 -182.624,77.238 DS2.10@-180.59,75.204 -179.017,73.631 -165.307,73.631 -161.7,77.238 -151.636,77.238 DS3.10@-149.602,75.204
G: DS1.5 DS2.5 DS3.5 R10.2 | length 104.6
  Top Layer w0.254: R10.2@-232.965,71.022 v1(-231.802,71.022) ; v1(-211.299,67.916) -208.225,67.916 -206.498,66.189 DS1.5@-206.498,64.844
  Bottom Layer w0.254: v1(-231.802,71.022) -228.857,71.022 -227.199,69.364 -227.199,65.35 -226.257,64.408 -219.506,64.408 -216.76,67.154 -213.89,67.154 -213.128,67.916 v1(-211.299,67.916) ; DS1.5@-206.498,64.844 -205.103,66.239 -200.656,66.239 -196.491,62.074 -178.28,62.074 DS2.5@-175.51,64.844 -173.886,66.468 -167.636,66.468 -162.734,61.566 -147.8,61.566 DS3.5@-144.522,64.844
